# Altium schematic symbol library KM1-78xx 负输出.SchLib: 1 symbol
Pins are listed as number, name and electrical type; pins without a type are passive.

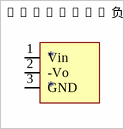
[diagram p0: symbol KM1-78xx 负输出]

## KM1-78xx 负输出
designator *
footprint Model Name (Footprint not found)
pins: 1 Vin, 2 -Vo, 3 GND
